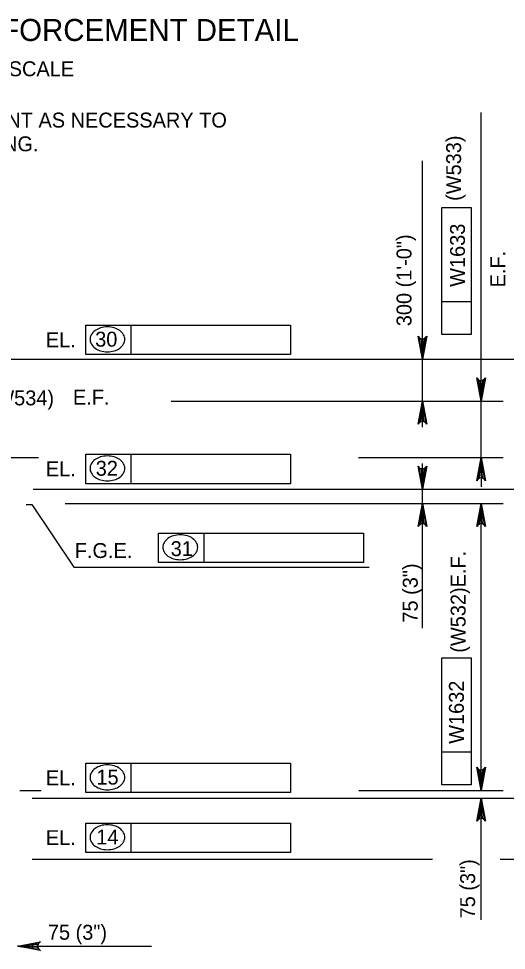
# Model space of a CAD drawing. Extents: x 634540 to 640306, y 296059 to 300275.
# Drawn here: x 639742.9 to 639841, y 297947.4 to 298134.8 of the extents above; entities that cross this region are included whole.
import ezdxf

# ---------------------------------------------------------------- set-up
doc = ezdxf.new("R2010")
doc.units = 0
doc.layers.add('3', color=7, linetype='Continuous')
doc.layers.add('4', color=7, linetype='Continuous')

msp = doc.modelspace()

# ---------------------------------------------------------------- linework, layer by layer
at = {"layer": '3'}
msp.add_line((639744.4, 298037.1), (639745.53, 298037.1), dxfattribs=at)
at = {"layer": '4'}
for p, q in [((639835.94, 298068.53), (639835.94, 298115.93)), ((639824.13, 298052.62), (639824.13, 298106.24)), ((639828.05, 298071.27), (639828.05, 298096.81)), ((639828.05, 298096.81), (639833.95, 298096.81)), ((639833.95, 298096.81), (639833.95, 298071.27)), ((639833.95, 298077.87), (639828.05, 298077.87)), ((639756.38, 298073.15), (639797.59, 298073.15)), ((639756.38, 298067.25), (639756.38, 298073.15)), ((639765.55, 298067.25), (639765.55, 298073.15)), ((639797.59, 298073.15), (639797.59, 298067.25)), ((639833.95, 298071.27), (639828.05, 298071.27)), ((639835.94, 298060.86), (639835.94, 298068.53)), ((639673.87, 298066.32), (639871.21, 298066.32)), ((639797.59, 298067.25), (639756.38, 298067.25)), ((639773.58, 298057.91), (639840.37, 298057.91)), ((639835.94, 298046.53), (639835.94, 298057.91)), ((639756.38, 298047.19), (639797.59, 298047.19)), ((639756.38, 298041.28), (639756.38, 298047.19)), ((639765.55, 298041.28), (639765.55, 298047.19)), ((639797.59, 298047.19), (639797.59, 298041.28)), ((639732.91, 298046.53), (639746.89, 298046.53)), ((639811.29, 298046.53), (639840.37, 298046.53)), ((639824.13, 298012.18), (639824.13, 298045.36)), ((639835.94, 298043.58), (639835.94, 298040.63)), ((639797.59, 298041.28), (639756.38, 298041.28)), ((639745.79, 298040.17), (639859.33, 298040.17)), ((639745.53, 298037.1), (639753.99, 298024.5)), ((639752.27, 298037.31), (639840.37, 298037.31)), ((639835.94, 297982.53), (639835.94, 298034.35)), ((639771.04, 298025.43), (639771.04, 298031.33)), ((639771.04, 298031.33), (639812.25, 298031.33)), ((639780.21, 298025.43), (639780.21, 298031.33)), ((639812.25, 298031.33), (639812.25, 298025.43)), ((639753.99, 298024.5), (639813.43, 298024.5)), ((639812.25, 298025.43), (639771.04, 298025.43)), ((639828.05, 297980.69), (639828.05, 298006.23)), ((639828.05, 298006.23), (639833.95, 298006.23)), ((639833.95, 298006.23), (639833.95, 297980.69)), ((639833.95, 297987.28), (639828.05, 297987.28)), ((639756.38, 297985.05), (639797.59, 297985.05)), ((639756.38, 297979.14), (639756.38, 297985.05)), ((639765.55, 297979.14), (639765.55, 297985.05)), ((639797.59, 297985.05), (639797.59, 297979.14)), ((639743.14, 297979.58), (639747.41, 297979.58)), ((639811.36, 297979.58), (639840.37, 297979.58)), ((639833.95, 297980.69), (639828.05, 297980.69)), ((639745.62, 297978.04), (639871.21, 297978.04)), ((639797.59, 297979.14), (639756.38, 297979.14)), ((639835.94, 297953.51), (639835.94, 297975.09)), ((639756.38, 297972.99), (639797.59, 297972.99)), ((639756.38, 297967.09), (639756.38, 297972.99)), ((639765.55, 297967.09), (639765.55, 297972.99)), ((639797.59, 297972.99), (639797.59, 297967.09)), ((639797.59, 297967.09), (639756.38, 297967.09)), ((639745.62, 297965.74), (639826.16, 297965.74)), ((639839.76, 297965.74), (639871.21, 297965.74)), ((639745.59, 297948.26), (639748.54, 297948.26)), ((639748.54, 297948.26), (639769.65, 297948.26))]:
    msp.add_line(p, q, dxfattribs=at)
for points in [[(639824.13, 298066.32), (639823.26, 298070.98), (639823.5, 298070.62), (639823.82, 298070.44), (639824.13, 298070.38), (639824.44, 298070.44), (639824.75, 298070.62), (639825, 298070.98), (639824.13, 298066.32), (639824.75, 298070.62), (639824.44, 298070.44), (639824.13, 298066.32), (639824.13, 298070.38), (639823.82, 298070.44), (639824.13, 298066.32), (639823.5, 298070.62)], [(639835.94, 298057.91), (639835.07, 298062.57), (639835.32, 298062.21), (639835.63, 298062.02), (639835.94, 298061.97), (639836.25, 298062.02), (639836.57, 298062.21), (639836.81, 298062.57), (639835.94, 298057.91), (639836.57, 298062.21), (639836.25, 298062.02), (639835.94, 298057.91), (639835.94, 298061.97), (639835.63, 298062.02), (639835.94, 298057.91), (639835.32, 298062.21)], [(639824.13, 298057.91), (639825, 298053.25), (639824.75, 298053.6), (639824.44, 298053.79), (639824.13, 298053.84), (639823.82, 298053.79), (639823.5, 298053.6), (639823.26, 298053.25), (639824.13, 298057.91), (639823.5, 298053.6), (639823.82, 298053.79), (639824.13, 298057.91), (639824.13, 298053.84), (639824.44, 298053.79), (639824.13, 298057.91), (639824.75, 298053.6)], [(639835.94, 298046.53), (639836.81, 298041.87), (639836.57, 298042.23), (639836.25, 298042.42), (639835.94, 298042.47), (639835.63, 298042.42), (639835.32, 298042.23), (639835.07, 298041.87), (639835.94, 298046.53), (639835.32, 298042.23), (639835.63, 298042.42), (639835.94, 298046.53), (639835.94, 298042.47), (639836.25, 298042.42), (639835.94, 298046.53), (639836.57, 298042.23)], [(639824.13, 298040.17), (639823.26, 298044.83), (639823.5, 298044.48), (639823.82, 298044.29), (639824.13, 298044.24), (639824.44, 298044.29), (639824.75, 298044.48), (639825, 298044.83), (639824.13, 298040.17), (639824.75, 298044.48), (639824.44, 298044.29), (639824.13, 298040.17), (639824.13, 298044.24), (639823.82, 298044.29), (639824.13, 298040.17), (639823.5, 298044.48)], [(639824.13, 298037.31), (639825, 298032.65), (639824.75, 298033), (639824.44, 298033.19), (639824.13, 298033.24), (639823.82, 298033.19), (639823.5, 298033), (639823.26, 298032.65), (639824.13, 298037.31), (639823.5, 298033), (639823.82, 298033.19), (639824.13, 298037.31), (639824.13, 298033.24), (639824.44, 298033.19), (639824.13, 298037.31), (639824.75, 298033)], [(639835.94, 298037.31), (639836.81, 298032.65), (639836.57, 298033), (639836.25, 298033.19), (639835.94, 298033.24), (639835.63, 298033.19), (639835.32, 298033), (639835.07, 298032.65), (639835.94, 298037.31), (639835.32, 298033), (639835.63, 298033.19), (639835.94, 298037.31), (639835.94, 298033.24), (639836.25, 298033.19), (639835.94, 298037.31), (639836.57, 298033)], [(639835.94, 297979.58), (639835.07, 297984.24), (639835.32, 297983.88), (639835.63, 297983.7), (639835.94, 297983.64), (639836.25, 297983.7), (639836.57, 297983.88), (639836.81, 297984.24), (639835.94, 297979.58), (639836.57, 297983.88), (639836.25, 297983.7), (639835.94, 297979.58), (639835.94, 297983.64), (639835.63, 297983.7), (639835.94, 297979.58), (639835.32, 297983.88)], [(639835.94, 297978.04), (639836.81, 297973.38), (639836.57, 297973.74), (639836.25, 297973.92), (639835.94, 297973.98), (639835.63, 297973.92), (639835.32, 297973.74), (639835.07, 297973.38), (639835.94, 297978.04), (639835.32, 297973.74), (639835.63, 297973.92), (639835.94, 297978.04), (639835.94, 297973.98), (639836.25, 297973.92), (639835.94, 297978.04), (639836.57, 297973.74)], [(639742.63, 297948.26), (639747.29, 297949.13), (639746.93, 297948.89), (639746.75, 297948.57), (639746.69, 297948.26), (639746.75, 297947.95), (639746.93, 297947.64), (639747.29, 297947.39), (639742.63, 297948.26), (639746.93, 297947.64), (639746.75, 297947.95), (639742.63, 297948.26), (639746.69, 297948.26), (639746.75, 297948.57), (639742.63, 297948.26), (639746.93, 297948.89)]]:
    msp.add_lwpolyline(points, dxfattribs=at)
for points in [[(639835.45, 298060.86), (639836.43, 298060.86), (639835.94, 298057.91)], [(639823.64, 298054.95), (639824.62, 298054.95), (639824.13, 298057.91)], [(639835.45, 298043.58), (639836.43, 298043.58), (639835.94, 298046.53)], [(639823.64, 298043.13), (639824.62, 298043.13), (639824.13, 298040.17)], [(639823.64, 298034.35), (639824.62, 298034.35), (639824.13, 298037.31)], [(639835.45, 298034.35), (639836.43, 298034.35), (639835.94, 298037.31)], [(639835.45, 297982.53), (639836.43, 297982.53), (639835.94, 297979.58)], [(639835.45, 297975.09), (639836.43, 297975.09), (639835.94, 297978.04)], [(639745.59, 297948.75), (639745.59, 297947.77), (639742.63, 297948.26)]]:
    msp.add_lwpolyline(points, close=True, dxfattribs=at)
for centre, radius, start, end in [((639759.08, 298070.31), 1.83, 149.9767, 180), ((639759.88, 298069.84), 2.76, 125.6316, 149.9767), ((639760.41, 298069.11), 3.66, 106.5358, 125.6316), ((639760.75, 298067.95), 4.87, 90, 106.5358), ((639760.75, 298067.95), 4.87, 73.4642, 90), ((639761.1, 298069.11), 3.66, 54.3684, 73.4642), ((639761.63, 298069.84), 2.76, 30.0233, 54.3684), ((639762.43, 298070.31), 1.83, 0, 30.0233), ((639759.08, 298070.31), 1.83, 180, 210.0233), ((639759.88, 298070.77), 2.76, 210.0233, 234.3684), ((639761.63, 298070.77), 2.76, 305.6316, 329.9767), ((639762.43, 298070.31), 1.83, 329.9767, 0), ((639760.41, 298071.51), 3.66, 234.3684, 253.4642), ((639760.75, 298072.67), 4.87, 253.4642, 270), ((639760.75, 298072.67), 4.87, 270, 286.5358), ((639761.1, 298071.51), 3.66, 286.5358, 305.6316), ((639760.75, 298041.98), 4.87, 90, 106.5358), ((639760.75, 298041.98), 4.87, 73.4642, 90), ((639759.08, 298044.34), 1.83, 149.9767, 180), ((639759.88, 298043.88), 2.76, 125.6316, 149.9767), ((639760.41, 298043.14), 3.66, 106.5358, 125.6316), ((639761.1, 298043.14), 3.66, 54.3684, 73.4642), ((639761.63, 298043.88), 2.76, 30.0233, 54.3684), ((639762.43, 298044.34), 1.83, 0, 30.0233), ((639759.08, 298044.34), 1.83, 180, 210.0233), ((639759.88, 298044.81), 2.76, 210.0233, 234.3684), ((639761.63, 298044.81), 2.76, 305.6316, 329.9767), ((639762.43, 298044.34), 1.83, 329.9767, 0), ((639760.41, 298045.54), 3.66, 234.3684, 253.4642), ((639760.75, 298046.71), 4.87, 253.4642, 270), ((639760.75, 298046.71), 4.87, 270, 286.5358), ((639761.1, 298045.54), 3.66, 286.5358, 305.6316), ((639774.54, 298028.02), 2.76, 125.6316, 149.9767), ((639775.07, 298027.29), 3.66, 106.5358, 125.6316), ((639775.41, 298026.13), 4.87, 90, 106.5358), ((639775.41, 298026.13), 4.87, 73.4642, 90), ((639775.76, 298027.29), 3.66, 54.3684, 73.4642), ((639776.28, 298028.02), 2.76, 30.0233, 54.3684), ((639773.74, 298028.49), 1.83, 149.9767, 180), ((639773.74, 298028.49), 1.83, 180, 210.0233), ((639777.09, 298028.49), 1.83, 0, 30.0233), ((639777.09, 298028.49), 1.83, 329.9767, 0), ((639774.54, 298028.95), 2.76, 210.0233, 234.3684), ((639775.07, 298029.69), 3.66, 234.3684, 253.4642), ((639775.41, 298030.85), 4.87, 253.4642, 270), ((639775.41, 298030.85), 4.87, 270, 286.5358), ((639775.76, 298029.69), 3.66, 286.5358, 305.6316), ((639776.28, 298028.95), 2.76, 305.6316, 329.9767), ((639759.08, 297982.2), 1.83, 149.9767, 180), ((639759.88, 297981.73), 2.76, 125.6316, 149.9767), ((639760.41, 297981), 3.66, 106.5358, 125.6316), ((639760.75, 297979.84), 4.87, 90, 106.5358), ((639760.75, 297979.84), 4.87, 73.4642, 90), ((639761.1, 297981), 3.66, 54.3684, 73.4642), ((639761.63, 297981.73), 2.76, 30.0233, 54.3684), ((639762.43, 297982.2), 1.83, 0, 30.0233), ((639759.08, 297982.2), 1.83, 180, 210.0233), ((639759.88, 297982.67), 2.76, 210.0233, 234.3684), ((639761.63, 297982.67), 2.76, 305.6316, 329.9767), ((639762.43, 297982.2), 1.83, 329.9767, 0), ((639760.41, 297983.4), 3.66, 234.3684, 253.4642), ((639760.75, 297984.56), 4.87, 253.4642, 270), ((639760.75, 297984.56), 4.87, 270, 286.5358), ((639761.1, 297983.4), 3.66, 286.5358, 305.6316), ((639759.88, 297969.68), 2.76, 125.6316, 149.9767), ((639760.41, 297968.95), 3.66, 106.5358, 125.6316), ((639760.75, 297967.79), 4.87, 90, 106.5358), ((639760.75, 297967.79), 4.87, 73.4642, 90), ((639761.1, 297968.95), 3.66, 54.3684, 73.4642), ((639761.63, 297969.68), 2.76, 30.0233, 54.3684), ((639759.08, 297970.15), 1.83, 149.9767, 180), ((639759.08, 297970.15), 1.83, 180, 210.0233), ((639762.43, 297970.15), 1.83, 0, 30.0233), ((639762.43, 297970.15), 1.83, 329.9767, 0), ((639759.88, 297970.61), 2.76, 210.0233, 234.3684), ((639760.41, 297971.35), 3.66, 234.3684, 253.4642), ((639761.1, 297971.35), 3.66, 286.5358, 305.6316), ((639761.63, 297970.61), 2.76, 305.6316, 329.9767), ((639760.75, 297972.51), 4.87, 253.4642, 270), ((639760.75, 297972.51), 4.87, 270, 286.5358)]:
    msp.add_arc(centre, radius, start, end, dxfattribs=at)

# ---------------------------------------------------------------- texts
for s, height, p in [('WEEPHOLE REINFORCEMENT DETAIL', 4.4294, (639690, 298130.34)), ('NO SCALE', 3, (639733.76, 298123.25)), ('ADJUST REINFORCEMENT AS NECESSARY TO', 3.0001, (639694.06, 298112.93)), ('ACCOMMODATE OPENING.', 3.0001, (639694.06, 298108.15)), ('EL.', 3, (639748.36, 298068.73)), ('30', 3, (639758.29, 298068.85)), ('(W534)', 3, (639736.86, 298057.04)), ('E.F.', 3, (639753.82, 298057.18)), ('EL.', 3, (639748.36, 298042.77)), ('32', 3, (639758.4, 298042.88)), ('F.G.E.', 3, (639754.18, 298026.33)), ('31', 3, (639773.48, 298026.71)), ('EL.', 3, (639748.36, 297980.62)), ('15', 3, (639758.54, 297980.74)), ('EL.', 3, (639748.36, 297968.57)), ('14', 3, (639758.51, 297968.69)), ('75 (3")', 3, (639748.77, 297949.53))]:
    msp.add_text(s, height=height, dxfattribs=at).set_placement(p)
for s, height, p in [('(W533)', 3, (639831.91, 298098.17)), ('W1633', 3, (639832.69, 298080.88)), ('300 (1\'-0")', 3.0001, (639821.93, 298072.96)), ('E.F.', 3, (639840.81, 298080.77)), ('(W532)E.F.', 3, (639832.82, 298007.27)), ('75 (3")', 3, (639823.18, 298013.33)), ('W1632', 3, (639832.47, 297988.94)), ('75 (3")', 3, (639834.73, 297953.82))]:
    msp.add_text(s, height=height, rotation=90, dxfattribs=at).set_placement(p)

doc.saveas('drawing.dxf')
